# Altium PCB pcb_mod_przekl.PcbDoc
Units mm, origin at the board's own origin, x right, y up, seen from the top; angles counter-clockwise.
Board outline 50.16 x 36.96 mm, 2 copper layers (Top Layer, Bottom Layer); 23 components, 15 nets, 72 pads, 0 vias.
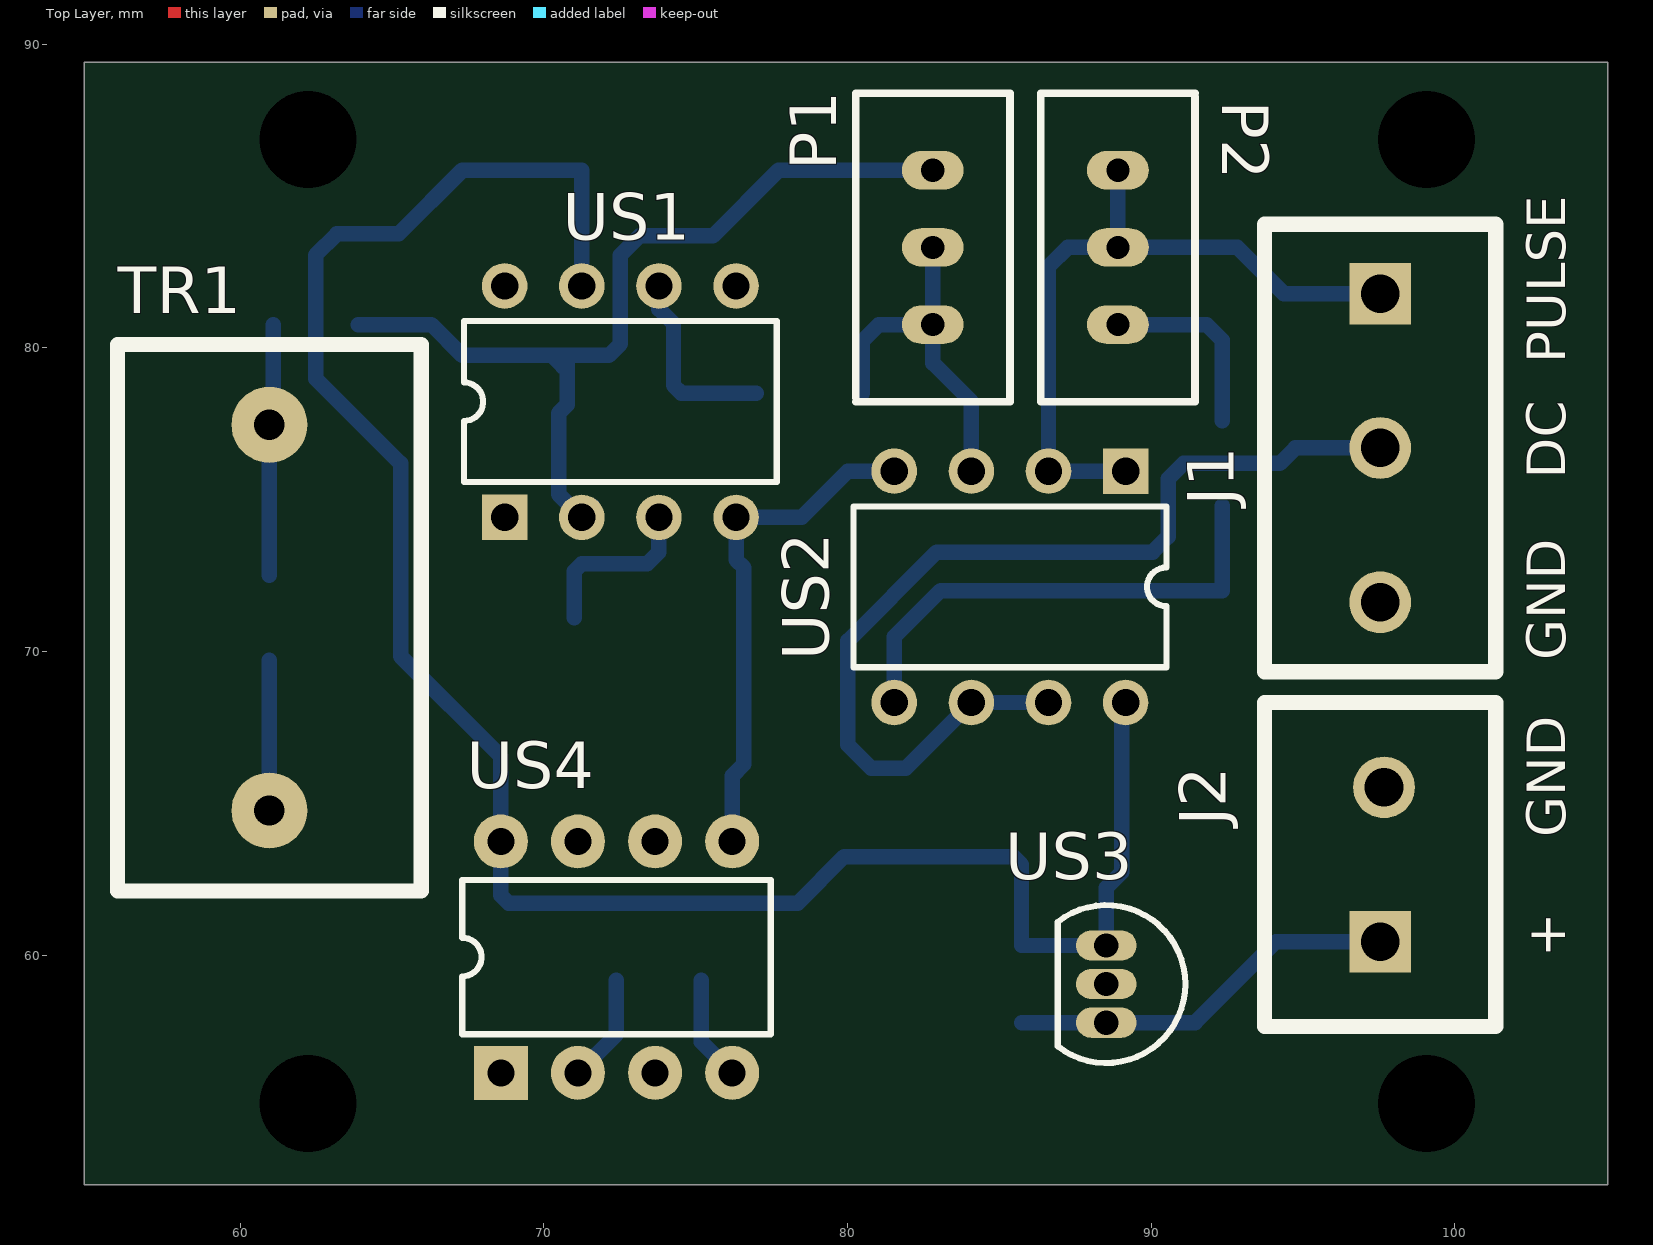
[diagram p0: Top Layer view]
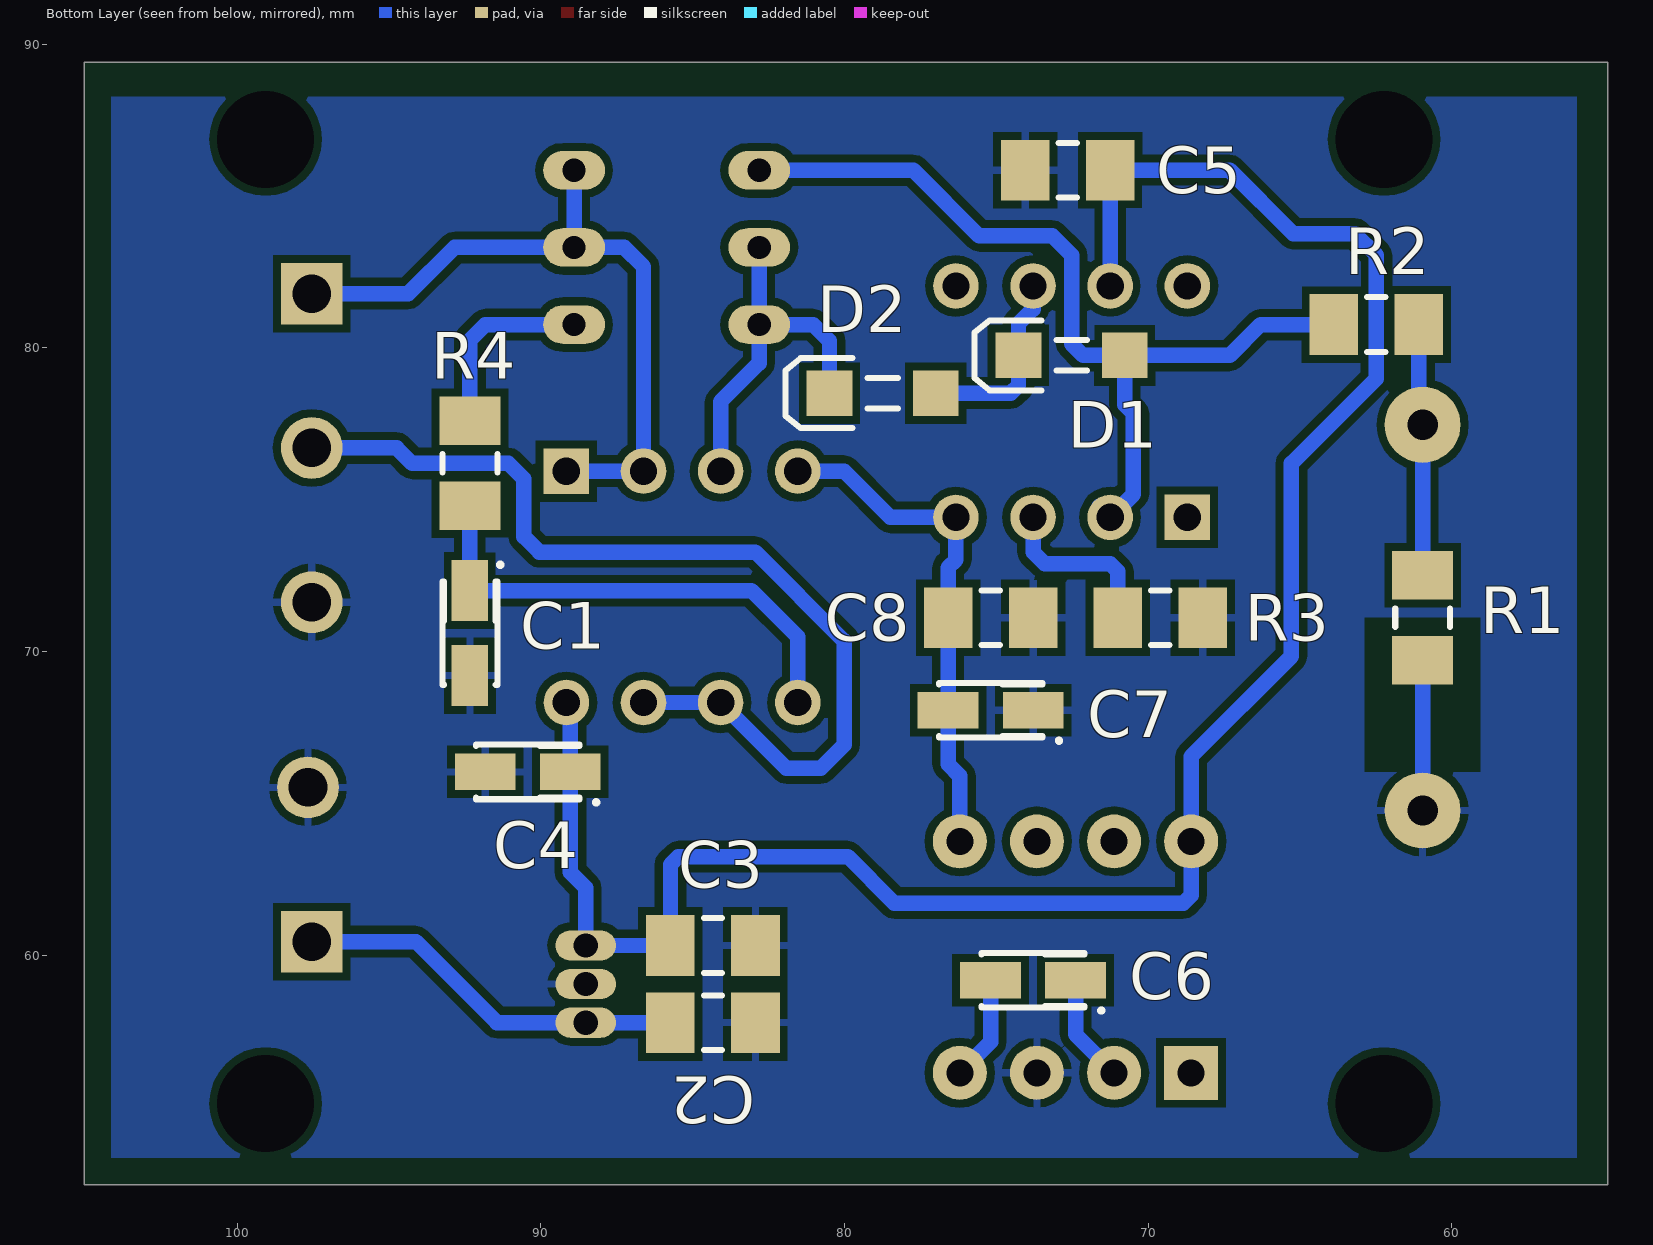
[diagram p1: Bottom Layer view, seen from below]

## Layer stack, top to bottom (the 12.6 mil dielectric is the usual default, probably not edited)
Top Layer: signal copper 0.0356
Dielectric: dielectric 0.32, FR-4, Dk 4.8
Bottom Layer: signal copper 0.0356

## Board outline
54.864,52.451 54.864,89.408 105.029,89.408 105.029,52.451

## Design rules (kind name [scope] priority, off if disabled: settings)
Clearance [All] p1: gap=0.254
PolygonConnect [All] p1: connectstyle=Relief reliefconductorwidth=0.254 reliefentries=4 polygonreliefangle="90 Angle"
RoutingVias [All] p1: holewidth=0.8 width=1.5 viastyle="Through Hole" minholewidth=0.8 minwidth=1.5 maxholewidth=0.8 maxwidth=1.5
SilkscreenOverComponentPads [All] p1: minsilkscreentomaskgap=0.254
SolderMaskExpansion [All] p1: expansion=0.102
Width [All] p1: maxlimit=2.54 minlimit=0.254 preferedwidth=0.508
27 further rules are at their usual default settings.

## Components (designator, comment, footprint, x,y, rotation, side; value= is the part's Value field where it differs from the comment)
C1 "10u/16V A" "Tantal A 3216-1206" 92.329,70.612 r270 bottom
C2 "100n" MELF-1206 84.328,57.785 r0 bottom
C3 "100n" MELF-1206 84.328,60.325 r0 bottom
C4 "10u/16V A" "Tantal A 3216-1206" 90.424,66.04 r0 bottom
C5 "100n" MELF-1206 72.644,85.852 r180 bottom
C6 "10u/16V A" "Tantal A 3216-1206" 73.787,59.182 r0 bottom
C7 "10u/16V A" "Tantal A 3216-1206" 75.184,68.072 r0 bottom
C8 "100n" MELF-1206 75.184,71.12 r0 bottom
D1 "1N4148" "dioda MINIMELF" 72.517,79.756 r0 bottom
D2 "1N4148" "dioda MINIMELF" 78.74,78.514 r0 bottom
J1 "ARK3" "ARK3 5mm" 97.536,76.708 r270 top
J2 "ARK2" "ARK2 5mm" 97.536,62.992 r90 top
P1 "200k" "helitrim 5x10mm" 82.804,83.312 r0 top
P2 "200k" "helitrim 5x10mm" 88.9,83.312 r180 top
R1 "51" MELF-1206 60.96,71.12 r90 bottom
R2 "1k" MELF-1206 62.484,80.772 r0 bottom
R3 "1k" MELF-1206 69.596,71.12 r0 bottom
R4 "1k" MELF-1206 92.329,76.2 r90 bottom
TR1 "ASM-010" "TALEMA AS10x" 60.96,71.12 r90 top
US1 "OP07" Q-8 72.517,78.232 r0 top
US2 "LM358" JG008 85.344,72.136 r180 top
US3 "78L09" 29-04 88.519,59.055 r180 top
US4 "ICL7660" DIP8 72.263,59.817 r90 top

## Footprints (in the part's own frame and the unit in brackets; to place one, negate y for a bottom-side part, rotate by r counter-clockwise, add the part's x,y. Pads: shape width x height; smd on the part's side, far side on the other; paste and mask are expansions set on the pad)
29-04 [mm] "TO, Flat Index; 3 In-Line, Axial Leads; Body Dia. 4.8mm; Leads 0.48 x 0.5 mm (max)"
  oval 2x1 hole 0.8: 1(0,-1.27) 2(0,0) 3(0,1.27)
  silkscreen extent -2.6,-2.6 1.6,2.6
"ARK2 5mm" [mil]
  rect 80x80 hole 50: 1(-100,0)
  round 80 hole 50: 2(100,-5)
  silkscreen extent -210,-150 210,150, body extent -220,-160 220,160, height 394
"ARK3 5mm" [mil]
  rect 80x80 hole 50: 1(-200,0)
  round 80 hole 50: 2(0,0) 3(200,0)
  silkscreen extent -290,-150 290,150, body extent -300,-160 300,160, height 394
"dioda MINIMELF" [mm] "SMT LED; 2 Flat Leads"
  rect 1.5x1.5 smd: 1(-1.75,0) 2(1.75,0)
  silkscreen extent -0.5,-1.15 3.2,1.15
DIP8 [mil]
  rect 70x70 hole 35: 1(-145,145)
  round 70 hole 35: 2(-145,45) 3(-145,-55) 4(-145,-155) 5(155,-155) 6(155,-55) 7(155,45) 8(155,145)
  silkscreen extent -95,-205 105,195, body extent -184,-194 194,184, height 197
"helitrim 5x10mm" [mil]
  oval 80x50 hole 30: a(0,-100) b(0,100) c(0,0)
  silkscreen extent -100,-200 100,200, body extent -105,-205 105,205, height 354
JG008 [mm] "DIP; 8 Leads; Row Spacing 7.62 mm; Pitch 2.54 mm"
  rect 1.5x1.5 hole 0.9: 1(-3.81,-3.81)
  round 1.5 hole 0.9: 2(-1.27,-3.81) 3(1.27,-3.81) 4(3.81,-3.81) 5(3.81,3.81) 6(1.27,3.81) 7(-1.27,3.81) 8(-3.81,3.81)
  silkscreen extent -5.15,-2.65 5.15,2.65
MELF-1206 [mm] "Metal Electrode Face (MELF) Resistor; Body 3.2 x 1.8 mm (LxDia)"
  rect 1.6x2 smd: 1(-1.4,0) 2(1.4,0)
  silkscreen extent -0.3,-0.9 0.3,0.9, body extent -2.3,-1.1 2.3,1.1, height 1.85
Q-8 [mm] "DIP; 8 Leads; Row Spacing 7.62 mm; Pitch 2.54 mm"
  rect 1.5x1.5 hole 0.9: 1(-3.81,-3.81)
  round 1.5 hole 0.9: 2(-1.27,-3.81) 3(1.27,-3.81) 4(3.81,-3.81) 5(3.81,3.81) 6(1.27,3.81) 7(-1.27,3.81) 8(-3.81,3.81)
  silkscreen extent -5.15,-2.65 5.15,2.65
"TALEMA AS10x" [mm]
  round 2.5 hole 1: 1(-6.35,0) 2(6.35,0)
  silkscreen extent -9,-5 9,5
"Tantal A 3216-1206" [mm] "Capacitor, SM Tantalum; Body 3.2 x 1.6 mm (LxW typ)"
  rect 2x1.2 smd: 1(-1.4,0) 2(1.4,0)
  silkscreen extent -2.26,-0.9 1.7,1.01, body extent -1.8,-1 1.8,1, height 2.2

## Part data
C1 C4 C6 C7: library part "kond biegunowy", "Polarized Capacitor"
C2 C3 C5 C8: library part kondensator
D1 D2: library part Diode, "Default Diode"
P1 P2: library part "pot mont"
R1 R2 R3 R4: library part rezystor
TR1: library part "przek³adnik pr¹dowy"
US1: library part OP07EZ, "Ultra-Low Offset Voltage Operational Amplifier"
US2: library part LM358JG, "Dual Operational Amplifier"
US3: library part MC78L05ACP, "3-Terminal Low-Current Positive Fixed Voltage Regulator"

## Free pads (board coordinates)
  round 0 hole 3.2: 0(62.23,86.868) 0(99.06,55.118) 1(62.23,55.118) 1(99.06,86.868)

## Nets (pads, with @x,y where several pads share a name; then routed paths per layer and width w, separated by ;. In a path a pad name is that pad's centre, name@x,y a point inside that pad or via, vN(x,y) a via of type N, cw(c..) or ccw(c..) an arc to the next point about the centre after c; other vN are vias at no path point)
GND: C1.2 C2.1 C3.1 C4.2 C5.1 C7.1 C8.1 J1.3 J2.2 R1.1 R3.1 TR1.1 US3.2 US4.3 | length 5
  Bottom Layer w0.508: TR1.1 R1.1
NetC1_1: C1.1 R4.1 US2.5 | length 16.4
  Bottom Layer w0.508: US2.5 81.534,70.485 83.061,72.012 C1.1 R4.1
NetC2_2: C2.2 J2.1 US3.3 | length 12.9
  Bottom Layer w0.508: C2.2 US3.3 91.44,57.785 94.107,60.452 J2.1
NetC6_1: C6.1 US4.2 | length 3.6
  Bottom Layer w0.508: US4.2 72.387,57.401 C6.1
NetC6_2: C6.2 US4.4 | length 3.5
  Bottom Layer w0.508: C6.2 75.187,57.147 US4.4
NetD1_1: D1.1 P1.b R2.2 US1.2 | length 29.6
  Bottom Layer w0.508: R2.2 66.294,80.772 67.31,79.756 D1.1@70.259,79.756 ; D1.1@70.626,79.615 70.626,79.389 D1.1@70.259,79.756 ; US1.2@71.609,74.784 US1.2 70.485,75.184 70.485,77.851 70.767,78.133 D1.1 ; P1.b@81.788,85.852 77.724,85.852 75.565,83.693 73.152,83.693 72.517,83.058 72.517,80.137 72.136,79.756 D1.1 ; D1.1@70.259,79.756 D1.1
NetD1_2: D1.2 D2.1 US1.6 | length 6.3
  Bottom Layer w0.508: US1.6 73.787,81.28 74.267,80.8 D1.2 74.267,78.768 74.521,78.514 D2.1
NetD2_2: D2.2 P1.a P1.c US2.3 | length 12.3
  Bottom Layer w0.508: D2.2 80.49,80.236 81.026,80.772 P1.a ; P1.c@82.677,83.439 P1.c P1.a ; US2.3 84.074,78.232 82.804,79.502 P1.a
NetJ1_1: J1.1 P2.a P2.c US2.1 US2.2 | length 23.6
  Bottom Layer w0.508: P2.a P2.c ; US2.1 US2.2 86.614,82.677 87.249,83.312 P2.c ; J1.1 94.361,81.788 92.837,83.312 P2.c
NetJ1_2: J1.2 US2.6 US2.7 | length 32.9
  Bottom Layer w0.508: US2.7 US2.6 81.915,66.167 80.772,66.167 80.01,66.929 80.01,70.358 82.931,73.279 87.757,73.279 ; 88.138,73.279 87.757,73.279 ; J1.2 94.742,76.708 94.234,76.2 91.059,76.2 90.551,75.692 90.551,73.787 90.043,73.279 87.757,73.279
NetP2_b: P2.b R4.2 | length 6.3
  Bottom Layer w0.508: P2.b 91.821,80.772 92.329,80.264 R4.2
NetR1_2: R1.2 R2.1 TR1.2 | length 8.1
  Bottom Layer w0.508: R1.2 TR1.2 ; TR1.2@61.084,77.594 R2.1
NetR3_2: R3.2 US1.3 | length 5.7
  Bottom Layer w0.508: R3.2 70.996,72.647 71.247,72.898 73.406,72.898 73.787,73.279 US1.3
VCC: C3.2 C4.1 C5.2 US1.7 US2.8 US3.1 US4.8 | length 69.2
  Bottom Layer w0.508: US4.8@68.326,64.008 US4.8 ; US1.7@71.244,82.045 C5.2 67.31,85.852 65.215,83.757 63.182,83.757 62.484,83.058 62.484,78.994 65.278,76.2 65.278,69.85 68.58,66.548 US4.8 ; US2.8@89.024,68.196 C4.1 89.024,62.735 88.519,62.23 US3.1 C3.2 85.725,60.328 85.725,62.992 85.468,63.249 79.886,63.249 78.359,61.722 68.834,61.722 68.58,61.976 US4.8
VEE: C7.2 C8.2 US1.4 US2.4 US4.5 | length 16.8
  Bottom Layer w0.508: US4.5 76.2,65.913 76.584,66.297 C8.2 76.584,72.768 76.327,73.025 US1.4 78.486,74.422 80.01,75.946 US2.4
pads on no net: US1.1 US1.5 US1.8 US4.1 US4.6 US4.7

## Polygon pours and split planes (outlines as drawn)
GND on Bottom Layer "Bottom Layer-No Net" (solid): 55.88,53.34 104.14,53.34 104.14,88.265 55.88,88.265

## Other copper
Bottom Layer:
  pour cut-out: 59.055,71.12 62.865,71.12 62.865,66.04 59.055,66.04

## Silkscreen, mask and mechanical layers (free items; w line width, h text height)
Top Overlay:
  text "PULSE" at 103.632,79.502 h1.27 r90
  text "DC" at 103.632,75.692 h1.27 r90
  text "GND" at 103.632,69.723 h1.27 r90
  text "GND" at 103.632,63.881 h1.27 r90
  text "+" at 103.632,59.944 h1.27 r90
Mechanical 1:
  the board outline again, w0.508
